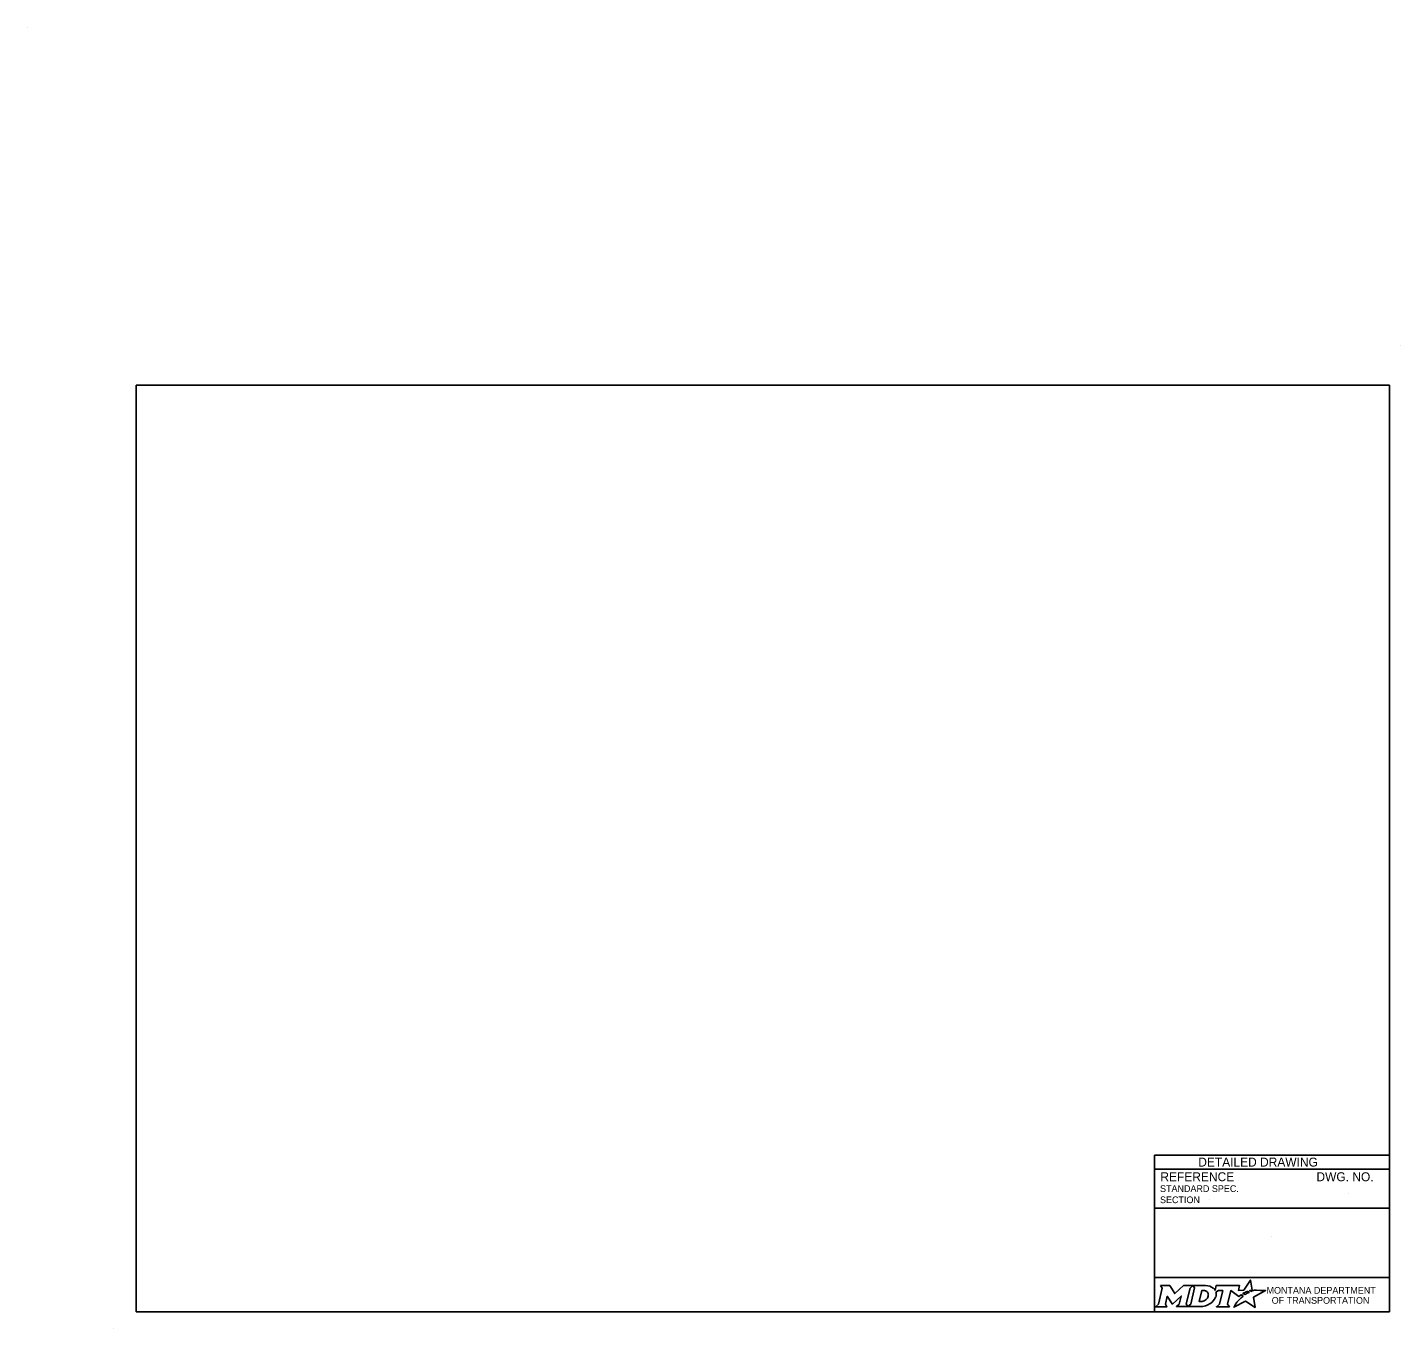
# Model space of a CAD drawing. Extents: x 49991.4 to 50021, y 49987.6 to 50011.4.
# Drawn here: x 50008.76 to 50021.04, y 49999.74 to 50011.36 of the extents above; entities that cross this region are included whole.
import ezdxf

# ---------------------------------------------------------------- set-up
doc = ezdxf.new("R2010")
doc.units = 0
for name, color, linetype in [('Default', 7, 'Continuous'), ('Level 1', 7, 'Continuous'), ('Level 4', 7, 'Continuous')]:
    doc.layers.add(name, color=color, linetype=linetype)

msp = doc.modelspace()

# ---------------------------------------------------------------- linework, layer by layer
at = {"layer": 'Default'}
for points in [[(50018.893, 50000.121), (50018.907, 50000.097), (50018.874, 49999.954), (50018.848, 49999.931), (50018.95, 49999.931), (50018.936, 49999.954), (50018.952, 50000.024), (50018.996, 49999.955), (50019.002, 49999.955), (50019.077, 50000.025), (50019.06, 49999.954), (50019.035, 49999.932), (50019.137, 49999.932), (50019.123, 49999.955), (50019.156, 50000.097)], [(50019.156, 50000.097), (50019.182, 50000.121), (50019.099, 50000.121), (50019.02, 50000.048), (50018.975, 50000.12), (50018.893, 50000.121)], [(50019.295, 50000.121), (50019.182, 50000.121), (50019.196, 50000.098), (50019.163, 49999.954), (50019.137, 49999.932), (50019.248, 49999.932)], [(50019.7, 50000.068), (50019.69, 50000.074), (50019.702, 50000.076), (50019.713, 50000.078), (50019.696, 50000.168), (50019.636, 50000.077), (50019.589, 50000.076), (50019.599, 50000.12), (50019.39, 50000.121), (50019.38, 50000.078), (50019.374, 50000.086)], [(50019.319, 50000.034), (50019.318, 50000.026), (50019.315, 50000.017), (50019.311, 50000.008), (50019.305, 50000.001), (50019.299, 49999.994), (50019.291, 49999.988), (50019.282, 49999.983), (50019.273, 49999.979), (50019.264, 49999.977), (50019.255, 49999.976), (50019.239, 49999.976), (50019.263, 50000.076), (50019.279, 50000.076), (50019.286, 50000.075), (50019.294, 50000.073), (50019.301, 50000.07), (50019.307, 50000.066), (50019.311, 50000.061), (50019.315, 50000.055), (50019.318, 50000.049), (50019.319, 50000.042), (50019.32, 50000.038), (50019.319, 50000.034)], [(50019.387, 50000.062), (50019.411, 50000.075), (50019.448, 50000.075), (50019.42, 49999.954), (50019.392, 49999.931), (50019.508, 49999.931), (50019.491, 49999.954), (50019.52, 50000.075), (50019.591, 50000.023), (50019.612, 50000.038), (50019.632, 50000.027)], [(50019.576, 49999.971), (50019.561, 49999.947), (50019.556, 49999.939), (50019.55, 49999.931), (50019.548, 49999.926), (50019.653, 49999.979), (50019.737, 49999.924), (50019.724, 50000.017), (50019.831, 50000.075), (50019.782, 50000.076), (50019.751, 50000.077), (50019.731, 50000.077), (50019.724, 50000.075), (50019.719, 50000.074), (50019.711, 50000.072), (50019.7, 50000.068)], [(50019.59, 49999.987), (50019.59, 49999.987)], [(50019.65, 50000.04), (50019.648, 50000.039), (50019.629, 50000.048), (50019.639, 50000.054), (50019.644, 50000.056), (50019.652, 50000.06), (50019.658, 50000.063), (50019.666, 50000.066), (50019.673, 50000.068), (50019.685, 50000.061), (50019.681, 50000.059), (50019.676, 50000.056), (50019.672, 50000.054), (50019.667, 50000.051), (50019.665, 50000.05), (50019.662, 50000.049), (50019.66, 50000.047), (50019.658, 50000.046), (50019.655, 50000.044), (50019.652, 50000.042), (50019.65, 50000.04)], [(50019.293, 49999.939), (50019.302, 49999.942), (50019.315, 49999.947), (50019.335, 49999.958)]]:
    msp.add_lwpolyline(points, dxfattribs=at)
for centre, radius, start, end in [((50019.274, 50000.059), 0.118, 300.9103, 339.1383), ((50019.319, 50000.042), 0.0709, 339.5329, 15.8582)]:
    msp.add_arc(centre, radius, start, end, dxfattribs=at)
for centre, major_axis, ratio, start_param, end_param in [((50019.293, 50000.073), (0.0834, -0.0037), 0.568097, 0.61298, 1.570796), ((50019.349, 50000.081), (0.0361, -0.0295), 0.469099, 1.225588, 1.570796), ((50019.583, 49999.979), (-0.00694, -0.00806), 0.008222, 0, 3.137361), ((50019.6, 49999.997), (-0.0098, -0.0102), 0.016458, 3.141593, 6.279097), ((50019.621, 50000.017), (-0.0112, -0.0097), 0.021651, 3.157348, 6.283185), ((50019.248, 50000.08), (0, 0.148), 0.987302, 3.139398, 3.456847)]:
    msp.add_ellipse(centre, major_axis=major_axis, ratio=ratio, start_param=start_param, end_param=end_param, dxfattribs=at)
at = {"layer": 'Level 1'}
for p, q in [((50008.765, 50011.363), (50008.765, 50011.363)), ((50021.038, 50008.524), (50021.038, 50008.524)), ((50009.537, 49999.736), (50009.537, 49999.736))]:
    msp.add_line(p, q, dxfattribs=at)
msp.add_lwpolyline([(50020.938, 50008.165), (50009.737, 50008.165), (50009.737, 49999.886), (50020.938, 49999.886)], close=True, dxfattribs=at)
at = {"layer": 'Level 4'}
for p, q in [((50020.938, 50001.286), (50018.838, 50001.286)), ((50018.838, 50001.286), (50018.838, 49999.886)), ((50020.938, 50001.161), (50018.838, 50001.161)), ((50019.332, 50000.886), (50019.332, 50000.886)), ((50020.574, 50000.946), (50020.574, 50000.946)), ((50020.938, 50000.811), (50018.838, 50000.811)), ((50019.888, 50000.562), (50019.888, 50000.562)), ((50020.938, 50000.193), (50018.838, 50000.193))]:
    msp.add_line(p, q, dxfattribs=at)

# ---------------------------------------------------------------- texts
at = {"layer": 'Default'}
for s, p in [('MONTANA DEPARTMENT', (50019.84, 50000.047)), ('OF TRANSPORTATION', (50019.886, 49999.957))]:
    msp.add_text(s, height=0.06, rotation=360, dxfattribs=at).set_placement(p)
at = {"layer": 'Level 4'}
for s, height, p in [('DETAILED DRAWING', 0.0799, (50019.23, 50001.183)), ('REFERENCE', 0.08, (50018.891, 50001.052)), ('DWG. NO.', 0.08, (50020.286, 50001.052)), ('STANDARD SPEC.', 0.06, (50018.888, 50000.956)), ('SECTION', 0.06, (50018.888, 50000.856))]:
    msp.add_text(s, height=height, dxfattribs=at).set_placement(p)

doc.saveas('drawing.dxf')
